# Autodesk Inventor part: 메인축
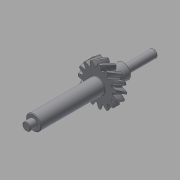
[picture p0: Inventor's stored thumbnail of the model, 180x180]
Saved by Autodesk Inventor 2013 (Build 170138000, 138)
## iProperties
Created: 2016-12
Part Number: 메인축
Material: 강철, 탄소
Document SubType Name: Modeling
Designer: mduedu
Categories: <?xml version="1.0" encoding="UTF-16"?> <MemberInstance><Categories><FamilyTemplate><FamilyTemplateParameter ValueType="xs:double" Id="1" ObjectReferenceKey="da
Density: 7.87 g/cm^3
Mass: 199.398 g
Surface Area: 86.9132 cm^2
Volume: 25.3364 cm^3
CustomPartVersion: 1
Author: mduedu
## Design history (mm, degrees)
sketch "Sketch1"
  geometry: C1 r 19.321 at (0, 0)
  constraints: 1 centre point
  dimensions: "d0" = 38.64102 diameter of C1 (= da_da)
extrude "Extrusion1" new body sketch "Sketch1" distance "d1" = 10 (= da_b); taper "d2" = 0 deg
workplane "Work Plane2"
sketch "Sketch2"
  geometry: C1 r 19.321 at (0, 0) reference; C2 r 17.321 at (0, 0)
  constraints: 1 centre point, 1 coincident
  dimensions: "d3" = 34.64102 diameter of C2 (= da_dw)
feature "피치 지름" sketch "Sketch2" dims "d4" = 10, "d5" = 0
workplane "Work Plane8"
workplane "Work Plane9"
feature "스퍼 기어" dims "da_b" = 10, "da_d" = 34.64102, "da_aw" = 43.87862, "da_da" = 38.64102, "da_df" = 29.64102, "da_dw" = 34.64102, angle "da_beta" = 30 deg, "da_lefttooth" = 0, "da_righttooth" = 10
sketch "스케치3"
  geometry: C1 r 7.5 at (0, 0); 1 further point
  constraints: 1 centre point, 1 coincident
  dimensions: "d49" = 15 diameter of C1
extrude "돌출2" join sketch "스케치3" distance "d50" = 64; taper "d51" = 0 deg
sketch "스케치4"
  geometry: C1 r 4 at (0, 0); 1 further point
  constraints: 1 centre point, 1 coincident
  dimensions: "d52" = 8 diameter of C1
extrude "돌출3" join sketch "스케치4" distance "d53" = 7; taper "d54" = 0 deg
sketch "스케치5"
  geometry: C1 r 7.5 at (0, 0) reference; 1 further point
extrude "돌출4" join sketch "스케치5" distance "d55" = 16; taper "d56" = 0 deg
sketch "스케치6"
  geometry: C1 r 4 at (0, 0); 1 further point
  constraints: 1 centre point, 1 coincident
  dimensions: "d57" = 8 diameter of C1
extrude "돌출5" join sketch "스케치6" distance "d58" = 30; taper "d59" = 0 deg
chamfer "모따기1" distance "d60" = 0.5; stored, may be unused: second distance "d61" = 2, angle "d62" = 45 deg
fillet "모깎기1" dims "d63" = 0.5
body "Solid1"
body "Srf1"
other parameters: "d16" = 43.87862 (= da_aw), "d17" = 0, "d34" = 12 deg (computed from da_z), "d39" = 0, "d41" = 0, "d43" = 43.87862 (= da_aw), "d46" = 43.87862 (= da_aw), "d47" = 0, "d48" = 0
